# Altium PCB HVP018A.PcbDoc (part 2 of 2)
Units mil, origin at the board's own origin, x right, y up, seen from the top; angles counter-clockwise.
Board outline 2060 x 1591 mil, 4 copper layers (Top Layer, MidLayer1, MidLayer2, Bottom Layer), stack 46.2 mil thick; 91 components, 51 nets, 302 pads, 340 vias.
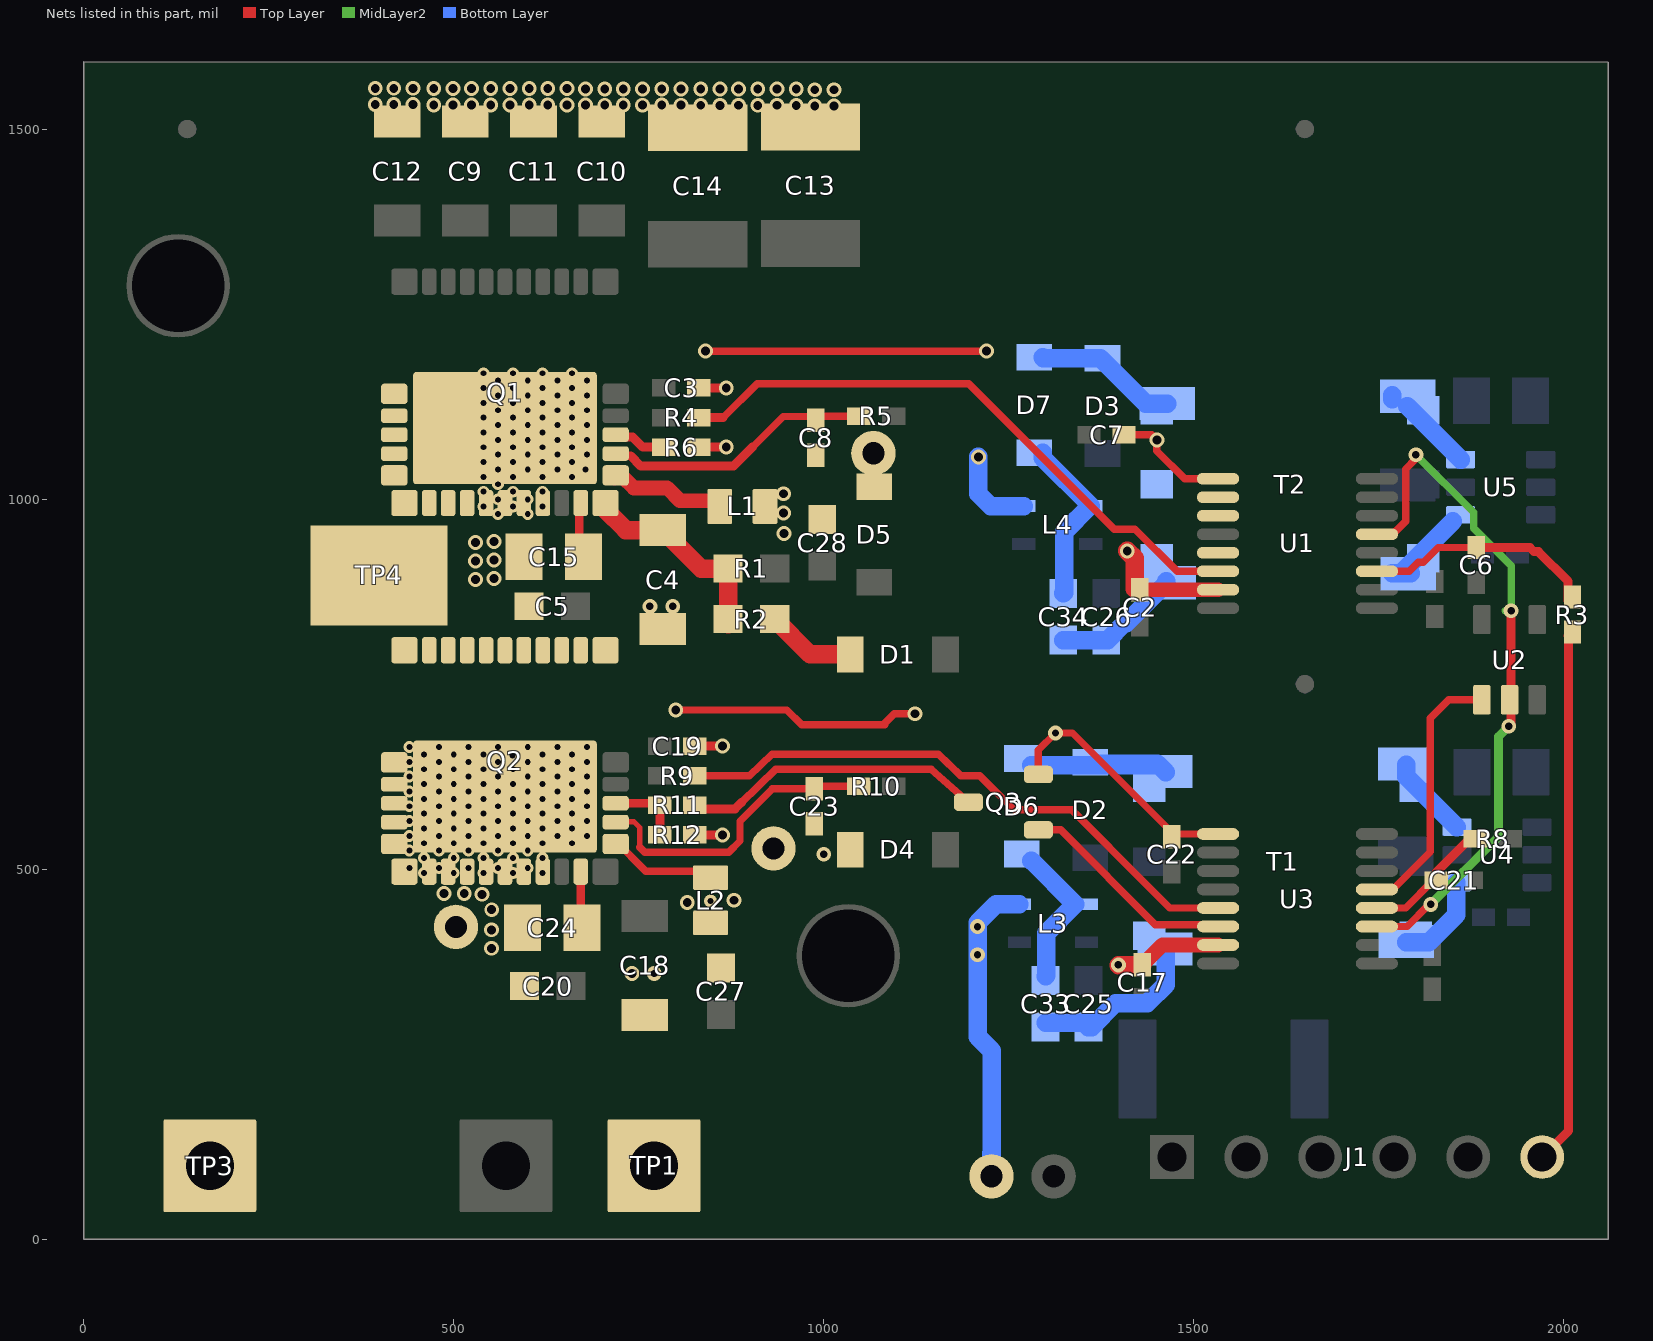
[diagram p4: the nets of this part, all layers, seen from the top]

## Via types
v1: diameter 16, hole 8, Top Layer to Bottom Layer, 182 vias
v2: diameter 20, hole 12, Top Layer to Bottom Layer, tented both sides, 80 vias
v3: diameter 20, hole 10, Top Layer to Bottom Layer, tented both sides, 40 vias
v4: diameter 20, hole 12, Top Layer to Bottom Layer, tented top, 18 vias
v5: diameter 20, hole 12.1, Top Layer to Bottom Layer, tented both sides, 14 vias
v6: diameter 20, hole 12, Top Layer to Bottom Layer, 4 vias
v7: diameter 22, hole 10, Top Layer to Bottom Layer, tented both sides, 1 vias
v8: diameter 18, hole 8, Top Layer to Bottom Layer, tented both sides, 1 vias

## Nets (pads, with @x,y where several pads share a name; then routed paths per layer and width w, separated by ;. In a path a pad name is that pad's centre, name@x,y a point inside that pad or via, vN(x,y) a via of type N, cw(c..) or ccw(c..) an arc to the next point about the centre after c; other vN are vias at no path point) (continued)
ISO_RET_H: C2.1 C3.1 C4.2 C5.2 C7.2 C8.2 C15.2 C28.2 D5.2 L1.1 L4.2 pad.2@1067,1062 Q1.12 Q1.13 Q1.14 Q1.15 Q1.16 Q1.17 Q1.18 Q1.19 Q1.20 Q1.21 Q1.22 Q1.23 Q1.24 Q1.33@569.24,1095.94 Q2.1 Q2.2 Q2.3 Q2.4 Q2.5 Q2.6 Q2.7 Q2.8 Q2.9 Q2.10 Q2.11 R6.1 TP3.1 TP4.1 U1.9 U1.15 | length 904.6
  Top Layer w10: v6(840,1200) v6(1220,1200) ; C7.2@1405.62,1087 1443,1087 v5(1450,1080) 1450,1078.52 1450,1065 1487.5,1027.5 1501.02,1027.5 U1.9@1532.72,1027.5 ; C2.1@1427,867.5 C2.1@1427,877.62
  Top Layer w12: R6.1@830.86,1070.17 v2(868.24,1070.17) ; C3.1@830.86,1150.17 v2(868.24,1150.17)
  Top Layer w20: C2.1@1427,877.62 U1.15@1532.59,877.62
  Top Layer w25: v5(1410,930) 1420,920 C2.1@1420,878.62
  Bottom Layer w25: v2(1209,1057) 1209,1007 1225.41,990.59 L4.2@1270.32,990.59
  other v1: 560,980 600,980 540,990 580,990 620,990 560,999.72 600,999.72 540,1010 580,1010 620,1010 560,1020 540,1030 580,1030 620,1030 660,1030 560,1040 600,1040 640,1040 678.26,1039.8 540,1050 580,1050 620,1050 660,1050 560,1060 600,1060 640,1060 680,1060 540,1070 580,1070 620,1070 660,1070 560,1080 600,1080 640,1080 680,1080 540,1090 580,1090 620,1090 660,1090 560,1100 600,1100 640,1100 680,1100 540,1110 580,1110 620,1110 660,1110 560,1120 600,1120 640,1120 680,1120 540,1130 580,1130 620,1130 660,1130 560,1140 600,1140 640,1140 680,1140 540,1150 580,1150 620,1150 660,1150 560,1160 600,1160 640,1160 680,1160 540,1170 580,1170 620,1170 660,1170
  other v2: 946.24,953.69 945.39,981.17 945.39,1007.17
  other v3: 765,855 796,855
  other v5: 529.24,891.53 554.24,892.63 529.24,916.53 554.24,917.63 529.24,941.53 554.24,942.63
ISO_RET_H_B: C34.2 D7.2 L4.3 | length 239.9
  Bottom Layer w25: C34.2@1323.59,872.5 1324.74,873.65 1324.74,955.72 1359.61,990.59 L4.3@1360.87,990.59 D7.2@1295.59,1055.87 ; D7.2@1295.59,1055.87 1295.59,1062.53 D7.2@1295.59,1055.87
ISO_RET_L: C9.2 C10.2 C11.2 C12.2 C13.2 C14.2 C17.1 C18.2 C19.1 C20.2 C22.2 C23.2 C24.2 C27.2 D4.2 L2.1 L3.2 pad.2@503,422 pad.2@932,528 pad.2@1226.59,85 Q2.12 Q2.13 Q2.14 Q2.15 Q2.16 Q2.17 Q2.18 Q2.19 Q2.20 Q2.21 Q2.22 Q2.23 Q2.24 Q2.33@569.24,597.94 Q3.2 R12.1 TP1.1 U3.9 U3.15 | length 1347.1
  Top Layer w10: v6(800,715) 949.88,715 970,695 1082.75,695 ; 1082.98,697.98 1095,710 v6(1123.35,710) ; Q3.2@1289.93,627.9 1289.93,660.93 v3(1313,684) 1336,684 1472.5,547.5 U3.9@1520.99,547.5
  Top Layer w12: R12.1@825.76,546.24 v2(863.14,546.24) ; C19.1@825.76,666.24 v2(863.14,666.24)
  Top Layer w20: C17.1@1430.59,370.62 1457.5,397.5 U3.15@1532.72,397.5
  Top Layer w25: v3@1398.47,370.3 C17.1@1430.09,370.3
  Bottom Layer w10: v3(1207.62,422.38) 1207.62,427.44 v3@1207.99,427.81
  Bottom Layer w25: pad.2@1226.59,85 1227,153 1227,254.59 1207.93,273.66 v3@1207.97,384.38 ; L3.2@1264.32,452.59 1232.99,452.81 1207.99,427.81 v3@1207.99,422.38 ; v3@1207.97,384.38 v3@1207.99,422.38 ; v3@1207.97,384.38 v3@1207.99,422.38
  other v1: 460,495 500,495 540,495 580,495 620,495 440,501.72 480,501.72 520,501.72 560,501.72 600,501.72 460,515 500,515 540,515 580,515 620,515 440,525 480,525 520,525 560,525 600,525 460,535 500,535 540,535 580,535 620,535 660,535 440,545 480,545 520,545 560,545 600,545 640,545 680,545 460,555 500,555 540,555 580,555 620,555 660,555 440,565 480,565 520,565 560,565 600,565 640,565 680,565 460,575 500,575 540,575 580,575 620,575 660,575 440,585 480,585 520,585 560,585 600,585 640,585 680,585 460,595 500,595 540,595 580,595 620,595 660,595 440,605 480,605 520,605 560,605 600,605 640,605 680,605 460,615 500,615 540,615 580,615 620,615 660,615 440,625 480,625 520,625 560,625 600,625 640,625 680,625 460,635 500,635 540,635 580,635 620,635 660,635 440,645 480,645 520,645 560,645 600,645 640,645 680,645 579.24,653.81 460,655 500,655 540,655 620,655 660,655 440,665 480,665 520,665 560,665 600,665 640,665 680,665
  other v2: 741,359 815.51,455 878.5,458 987.81,1531.04 1013.81,1531.09 704,1532.21 755,1532.21 807,1532.21 833.81,1532.09 859.81,1532.04 884.81,1532.09 910.81,1532.04 936.81,1532.09 962.81,1532.04 394,1532.95 419,1533 445,1532.95 473,1532.63 499,1532.58 524,1532.63 550,1532.58 576,1532.63 602,1532.58 627,1532.63 653,1532.58 678,1532.26 729,1532.26 781,1532.26 987.81,1553.09 1013.81,1553.09 833.81,1554.09 859.81,1554.09 884.81,1554.09 910.81,1554.09 936.81,1554.09 962.81,1554.09 394,1555 419,1555 445,1555 473,1554.63 499,1554.63 524,1554.63 550,1554.63 576,1554.63 602,1554.63 627,1554.63 653,1554.63 678,1554.26 704,1554.26 729,1554.26 755,1554.26 781,1554.26 807,1554.26
  other v3: 771,359 1398.09,370.68 1207.62,384.38 1000,520
  other v5: 551,393 551,418 551.24,445.17 538,466 487,467 514.24,467.17
  other v8: 847,457
ISO_RET_L_B: C33.2 D6.2 L3.3 | length 197
  Bottom Layer w25: D6.2@1280.59,511.53 1339.53,452.59 1300.44,413.5 1300.44,356.34 C33.2@1299.59,355.5
ISONC1: U1.10
ISONC2: U1.13
ISONC3: U1.11
ISONC4: T2.2
NetC4_1: C4.1 Q1.27 R1.2 R2.2 | length 274.4
  Top Layer w25: Q1.27@703.06,987.63 732.59,958.1 C4.1@782.24,958.1 834.17,906.17 R1.2@870.74,906.17 R2.2@870.74,837.92 ; R2.2@867.37,834.55 R2.2@870.74,831.17
NetC6_1: C6.1 R3.2 U1.3 | length 316.9
  Top Layer w10: U1.3@1747.28,902.5 1790.91,902.5 1803.28,914.87 1810.25,914.87 1830,934.62 C6.1@1881.59,934.62
  Top Layer w12: C6.1@1881.59,934.62 1954.21,934.62 1959.7,929.13 1965.46,929.13 2005.59,889 R3.2@2005.59,862.62
NetC8_1: C8.1 Q1.29 R5.2 | length 429.8
  Top Layer w10: 903.61,1070.17 945.06,1111.62 ; C8.1@989.38,1112 R5.2@1047.38,1112 ; 945.06,1111.62 989,1111.62 945.06,1111.62
  Top Layer w12: 903.61,1070.17 877.93,1044.49 752.92,1044.49 738.91,1058.5 ; 738.91,1058.5 716.84,1058.5 738.91,1058.5
NetC21_1: C21.1 R8.2 U3.4 | length 169.5
  Top Layer w10: U3.4@1747.28,447.5 1786.1,447.5 C21.1@1823.6,485 ; C21.1@1824.5,485 C21.1@1827.59,485
  Top Layer w12: C21.1@1827.59,485 1827.59,496.08 R8.2@1872.51,541
NetC23_1: C23.1 Q2.29 R10.2 | length 450.1
  Top Layer w7: Q2.29@711.75,567.5 Q2.29@715.24,564 ; 751.4,529.71 751.4,556.24 743.63,564 ; Q2.29@715.24,564 743.63,564 ; Q2.29@715.24,564 743.63,564
  Top Layer w10: 751.4,529.71 758.06,523.05 871.76,523.05 886.73,538.02 886.73,564.74 930.62,608.62 C23.1@987,608.62 ; C23.1@992.38,611 994.76,611 995.76,612 R10.2@1047.38,612 R10.2@1053.38,612
NetC25_2: C25.2 C33.1 pad.3@1460.95,392.08 T1.1 | length 308
  Bottom Layer w25: C25.2@1357.59,286.5 1361.8,286.5 1394.29,319 1437.15,319 1461.95,343.81 pad.3@1461.95,390.92 ; C25.2@1357.59,292.5 1299.59,292.5 C25.2@1357.59,292.5 ; C25.2@1357.59,292.5 1361.8,292.5 C25.2@1357.59,292.5 ; C25.2@1357.59,289.5 1361.8,289.5 C25.2@1357.59,289.5
NetC26_2: C26.2 C34.1 pad.3@1465.59,887 T2.1 | length 175.8
  Bottom Layer w25: C34.1@1323.59,809.5 C26.2@1381.59,809.5 1383.54,809.5 1406.47,832.44 1408.73,832.44 pad.3@1462.95,886.66 ; pad.3@1462.95,886.66 1462.95,888.92 pad.3@1462.95,886.66
NetD1_1: D1.1 R2.1 | length 116.3
  Top Layer w25: R2.1@933.73,837.92 981.48,790.17 D1.1@1030.22,790.17
NetD2_2: D2.2 D6.1 pad.3@1460.95,632.08 T1.3 | length 356.3
  Bottom Layer w25: pad.3@1448.56,640.47 D2.2@1370.59,640.47 ; pad.3@1460.95,632.08 1461.95,631.08 1450.56,642.47 1372.59,642.47 D2.2@1370.59,640.47 ; D2.2@1370.59,640.47 1280.59,640.47 D2.2@1370.59,640.47
NetD3_2: D3.2 D7.1 pad.3@1463.95,1129.08 T2.3 | length 281
  Bottom Layer w25: D7.1@1295.59,1191.47 1296.59,1190.47 D3.2@1373.59,1190.47 ; pad.3@1463.95,1129.08 T2.3@1434.98,1129.08 ; D3.2@1373.59,1190.47 T2.3@1434.98,1129.08 ; D3.2@1373.59,1190.47 T2.3@1434.98,1129.08
NetQ1_30: Q1.30 R6.2 | length 97.1
  Top Layer w12: R6.2@783.61,1070.17 755.34,1070.17 741.43,1084.09 ; 741.43,1084.09 716.84,1084.09 741.43,1084.09
NetQ2_30: Q2.30 R11.2 R12.2 | length 169.5
  Top Layer w12: Q2.30@711.75,593.09 Q2.30@715.83,589 ; R12.2@778.52,546.24 R11.2@778.52,586.24 R11.2@775.76,589 ; Q2.30@715.83,589 R11.2@775.76,589 ; Q2.30@715.83,589 R11.2@775.76,589
NetQ3_1: Q3.1 U3.14 | length 293.3
  Top Layer w10: Q3.1@1289.93,553.09 1319.91,553.09 1448,425 U3.14@1530.22,425
NetQ3_3: Q3.3 R11.1 | length 462.5
  Top Layer w10: 888.66,590 935,635 1145,635 Q3.3@1195.44,590.5
  Top Layer w12: 888.66,590 879.9,581.24 ; 879.9,581.24 825.76,581.24 879.9,581.24
NetR4_1: R4.1 U1.14 | length 825.8
  Top Layer w10: 864.17,1110.17 910,1156 1196,1156 1392.5,959.5 1420.5,959.5 1477.5,902.5 U1.14@1532.72,902.5
  Top Layer w12: R4.1@830.86,1110.17 864.17,1110.17
NetR9_1: R9.1 U3.13 | length 804
  Top Layer w10: R9.1@825.76,626.24 899.62,626.24 930,655 1155,655 1184.98,626.24 1210.76,626.24 1257,580 1335,580 1438,477 1467.5,447.5 U3.13@1532.72,447.5
NetT1_4: pad.3@1785.95,642.08 T1.4 U4.3 | length 112.6
  Bottom Layer w25: pad.3@1787.23,641.08 1787.23,624.98 U4.3@1855.46,556.75
NetT1_6: pad.3@1786.95,402.08 T1.6 U4.1 | length 126.2
  Bottom Layer w25: T1.6@1787.23,400.92 1817.51,400.92 1854.85,438.26 U4.1@1854.85,481.33
NetT2_4: pad.3@1788.95,1139.08 T2.4 U5.3 | length 113
  Bottom Layer w25: T2.4@1788.23,1125.63 U5.3@1860.46,1053.4 ; pad.3@1768.23,1134.63 1768.23,1140.08 pad.3@1768.23,1134.63
NetT2_6: pad.3@1789.45,899.08 T2.6 U5.1 | length 144.8
  Bottom Layer w25: pad.3@1782.32,902.32 U5.1@1850,970 ; pad.3@1768.23,899.92 1792.78,899.92 pad.3@1768.23,899.92
NetU1_5: U1.5 U2.2 U3.3 | length 922.4
  Top Layer w10: U3.3@1747.28,422.5 1788.17,422.5 1818.08,452.41 v3(1820,452.41) v3@1817.5,449.91 ; U1.5@1768.94,952.5 1786.33,969.89 1786.33,1040.66 1800,1054.33 v3(1800,1060)
  Top Layer w12: v3(1925.59,693) 1928.59,696 v3(1928.59,849)
  MidLayer2 w10: v3(1800,1060) 1878.09,981.91 1878.09,960.51 1928.59,910.01 v3(1928.59,849) v3@1921,849
  MidLayer2 w12: v3(1820,452.41) 1911.59,544 1911.59,679 v3(1925.59,693)
NetU2_1: U2.1 U3.5 | length 354
  Top Layer w10: U3.5@1747.28,472.5 1768.94,472.5 1819.59,523.15 1819.59,546 1819.59,704 1844.46,728.87 U2.1@1889.19,728.87
SW_H: L1.2 Q1.28 | length 164.1
  Top Layer w12: Q1.28@716.84,1024.61 Q1.28@716.84,1028.97
  Top Layer w20: L1.2@851,997.63 805.78,997.63 788.24,1015.17 743.24,1015.17 Q1.28@729.44,1028.97 ; Q1.28@729.44,1028.97 716.84,1028.97 717.39,1028.97 Q1.28@729.44,1028.97
SW_L: L2.2 Q2.28 | length 292.7
  Top Layer w10: Q2.28@718.97,538.03 759.66,497.34 ; Q2.28@718.97,538.03 718.51,538.03 Q2.28@718.97,538.03 ; Q2.28@718.97,538.03 759.66,497.34 ; 759.66,497.34 848,497.34 759.66,497.34
TOP_FET: J1.6 R3.1 | length 720.7
  Top Layer w12: J1.6@1970.59,111 2006.39,146.8 R3.1@2006.39,814.57 ; R3.1@2006.39,814.57 2005.59,815.38 R3.1@2006.39,814.57
VM12V_H: C15.1 Q1.26 | length 59.8
  Top Layer w12: C15.1@669.6,927.81 Q1.26@669.6,987.63
VM12V_L: C24.1 Q2.26 | length 55.8
  Top Layer w12: C24.1@663.73,441.17 C24.1@664.6,442.04 ; C24.1@671.6,442.04 Q2.26@671.6,496.57
pads on no net: FID1.1 FID2.1 FID3.1 FID4.1 FID5.1 FID6.1 LBL1.0 Q1.33@475.54,1060.94 Q1.33@475.54,1131.81 Q1.33@522.39,1060.94 Q1.33@522.39,1131.81 Q1.33@569.24,1060.94 Q1.33@569.24,1131.81 Q1.33@616.09,1060.94 Q1.33@616.09,1131.81 Q1.33@662.94,1060.94 Q1.33@662.94,1131.81 Q2.33@475.54,562.94 Q2.33@475.54,633.81 Q2.33@522.39,562.94 Q2.33@522.39,633.81 Q2.33@569.24,562.94 Q2.33@569.24,633.81 Q2.33@616.09,562.94 Q2.33@616.09,633.81 Q2.33@662.94,562.94 Q2.33@662.94,633.81 T1.2 U1.6 U1.7 U3.6 U3.7 U3.10 U3.11

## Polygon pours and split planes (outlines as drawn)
AGND on MidLayer1 "AGND_L02_P202" (solid, remove dead copper, pour order 202): 2046.59,63.59 2046.59,1315.41 2032,1330 1716.55,1330 1716.55,280.55 1608,172 1428.94,172 1419.59,162.65 1419.59,61.41 1431,50 2033,50
ISO_RET_L on MidLayer1 "ISO_RET_L_L02_P194" (solid, remove dead copper, pour order 194): 842.55,6.47 833.09,230.93 704.52,359.5 489.52,359.5 430.52,418.5 430.52,521 680.02,521 688.76,529.74 688.76,771.27 679.52,780.5 536.26,780.5 519.52,797.24 519.52,1120.5 760.52,1361.5 1053.52,1361.5 1059.52,1367.5 1059.52,1564.5 1051.35,1572.67 326.7,1572.67 315.52,1561.5 315.52,349.5 468.52,196.5 712.52,196.5 712.52,6.47
ISO_RET_L on MidLayer1 "MidLayer1-No Net 10" (solid, remove dead copper, pour order 152): 480.31,510 700,510 700,666 774,740 1506.99,740 1565,681.99 1565,271 1531,237 851,237 716.83,371.17 502.83,371.17 454,420 454,483.69
ISO_RET_H on MidLayer1 "MidLayer1-No Net" (solid, remove dead copper, pour order 150): 515,890.41 515,959.72 565.28,1010 698.2,1010 698.2,1149.2 774,1225 1513,1225 1563.46,1174.54 1563.46,832.46 1513,782 1295.05,782 1285,792.05 1285,824.98 1271.98,838 994.5,838 981.48,824.98 981.48,793.83 969.65,782 709.36,782 625.19,866.17 539.24,866.17
ISO_RET_H on MidLayer1 "MidLayer1-No Net 2" (solid, remove dead copper, pour order 148): 544.24,1183.17 692.24,1183.17 692.24,1013.17 533,1013.17 533,1183.17
ISO_RET_H on MidLayer1 "ISO_RET_H_L02_P222" (solid, remove dead copper, pour order 222): 111,8 99.73,19.26 99.73,124.73 105,130 235,130 241.46,123.54 241.46,17.46 232,8
HVBUS on MidLayer1 "HVBUS_L02_P228" (solid, remove dead copper, pour order 228): 511,8 499.73,19.26 499.73,124.73 505,130 635,130 641.46,123.54 641.46,17.46 632,8
ISO_RET_L on Bottom Layer "ISO_RET_L_L04_P216" (solid, remove dead copper, pour order 216): 315.76,679.83 315.76,344.24 338.17,321.83 676.83,321.83 825.76,470.76 825.76,671.83 744.76,752.83 388.76,752.83
ISO_RET_H on Bottom Layer "ISO_RET_H_L04_P214" (solid, remove dead copper, pour order 214): 316,1172 316,836.41 338.41,814 677.06,814 826,962.94 826,1164 745,1245 389,1245
AGND on Bottom Layer "AGND_L04_P072" (solid, remove dead copper, pour order 72): 1970.59,875 1990.59,875 2020.59,905 2020.59,1150 2005.59,1165 1930.59,1165 1920.59,1155 1920.59,890 1935.59,875
AGND on Bottom Layer "AGND_L04_P070" (solid, remove dead copper, pour order 70): 1924.59,401 1986.59,401 2014.59,429 2014.59,657 1976.7,694.89 1955.93,694.89 1923.59,662.54 1923.59,402
5V on Bottom Layer "5V_L04_P074" (solid, remove dead copper, pour order 74): 1752.6,1195 1879.59,1195 1905.59,1169 1905.59,310 1865.59,270 1780.59,270 1750.59,300 1750.59,1195
ISO_RET_H on Bottom Layer "ISO_RET_H_L04_P232" (solid, remove dead copper, pour order 232): 111,8 99.73,19.26 99.73,124.73 105,130 235,130 241.46,123.54 241.46,17.46 232,8
HVBUS on Bottom Layer "HVBUS_L04_P240" (solid, remove dead copper, pour order 240): 511,8 499.73,19.26 499.73,124.73 505,130 635,130 641.46,123.54 641.46,17.46 632,8
ISO_RET_L on Bottom Layer "ISO_RET_L_L04_P242" (solid, remove dead copper, pour order 242): 711,8 699.73,19.26 699.73,124.73 705,130 835,130 841.46,123.54 841.46,17.46 832,8
5V on MidLayer2 "5V_L03_P200" (solid, pour order 200): 2046.59,63.59 2046.59,1316.41 2033,1330 1730,1330 1730,294 1608,172 1428.94,172 1419.59,162.65 1419.59,61.41 1431,50 2033,50
ISO_RET_L on MidLayer2 "ISO_RET_L_L03_P198" (solid, remove dead copper, pour order 198): 841.46,-1 841.46,232.64 727.1,347 727.1,703 720.1,710 443.1,710 435.1,702 435.1,439 584.1,290 610.1,290 699.72,200.38 699.72,9 709.72,-1
HVBUS on MidLayer2 "HVBUS_L03_P190" (solid, remove dead copper, pour order 190): 650,10 650,200 393,457 393,721 279,835 279,1072 469,1262 1072,1262 1079,1269 1079,1395 1067,1407 267,1407 116,1256 116,764 220,660 220,420 499.72,140.28 499.72,10 630,10
ISO_RET_H on MidLayer2 "ISO_RET_H_L03_P158" (solid, remove dead copper, pour order 158): 747,1245 827,1165 827,935.94 762.24,871.17 534.24,871.17 515,890.41 515,1154 537.17,1176.17 601.17,1176.17 670,1245
ISO_RET_L on MidLayer2 "ISO_RET_L_L03_P142" (solid, remove dead copper, pour order 142): 526.24,709.88 526.24,393 726,393 798.03,465.03 798.03,701.97 790.12,709.88
ISO_RET_H on MidLayer2 "ISO_RET_H_L03_P238" (solid, remove dead copper, pour order 238): 111,8 99.73,19.26 99.73,124.73 105,130 235,130 241.46,123.54 241.46,17.46 232,8
ISO_RET_H on Top Layer "ISO_RET_H_L01_P182" (solid, remove dead copper, pour order 182): 241.46,17.46 241.46,216.54 214,244 214,699.61 291.48,777.08 732.62,777.08 732.62,830 640,830 620,850 620,1010 640,1030 701.24,1030 701.24,1193 411.49,1193 40,830 40,192 99.86,132.14 99.73,19.28 111,8 232,8
ISO_RET_L on Top Layer "ISO_RET_L_L01_P140" (solid, remove dead copper, pour order 140): 677.04,523.03 635.99,523 624,510.99 624,309 616,301 574,301 387,488 387,699 395.99,707.99 694,708.13 694,540.01
ISO_RET_L on Top Layer "ISO_RET_L_L01_P218" (solid, remove dead copper, pour order 218): 1119.29,472.16 1119.29,572.19 1104.48,587 928,587 898,557 898,484.63 886.37,473 812.51,473 805,465.49 805,405.07 830.28,379.79 830.28,378.64 831.09,377.83 831.09,348 840.09,339 931,339 935,343 935,445 962.16,472.16
ISO_RET_L on Top Layer "ISO_RET_L_L01_P186" (solid, remove dead copper, pour order 186): 727,301.5 727,370 789,370 789,301.5
ISO_RET_H on Top Layer "ISO_RET_H_L01_P184" (solid, remove dead copper, pour order 184): 751,803 751,866 814,866 814,803
HVBUS on Top Layer "HVBUS_L01_P170" (solid, remove dead copper, pour order 170): 1059.4,1391.3 1059.4,1275.3 1043.4,1259.3 389.83,1264.72 116,990.89 116,1164.1 165.95,1198.28 216.57,1356.87 267,1407.3 1043.4,1407.3
IN_L on Top Layer "IN_L_L01_P128" (solid, remove dead copper, pour order 128): 712.14,631 736.91,631 760.14,654.24 760.14,679 788,679 795.2,671.8 795.2,611.2 788,604 701,604 701,619.86
ISO_12V_L on Top Layer "ISO_12V_L_L01_P126" (solid, remove dead copper, pour order 126): 812,245 1024.72,245 1024.72,264.28 960.01,329 812,329
ISO_RET_L on Top Layer "ISO_RET_L_L01_P102" (solid, remove dead copper, pour order 102): 316,1481 316,1555 328,1567 1051,1567 1060,1558 1060,1485.39 1046.61,1472 325,1472
IN_H on Top Layer "IN_H_L01_P036" (solid, remove dead copper, pour order 36): 701.24,1123 751.56,1123 768.24,1139.67 768.24,1162.17 802.24,1162.17 802.24,1098.17 762.24,1098.17 738.24,1098.17 701.24,1098.17
ISO_RET_H on Top Layer "ISO_RET_H_L01_P067" (solid, remove dead copper, pour order 67): 902.24,1025.17 918.17,1025.17 973,1080 1212,1080 1228,1064 1228,988 1218.41,978.41 1042.41,978.41 1005.17,941.17 910.83,941.17 902.24,949.76
ISO_12V_H on Top Layer "ISO_12V_H_L01_P082" (solid, remove dead copper, pour order 82): 917.24,886.17 997.24,886.17 1010.41,873 1283,873 1292.68,882.68 1292.68,946.32 1287.83,951.17 1026.17,951.17 1004,929 916.36,929 912.24,924.87 912.24,891.17
HVBUS on Top Layer "HVBUS_L01_P224" (solid, remove dead copper, pour order 224): 511,8 499.73,19.26 499.73,124.73 505,130 635,130 641.46,123.54 641.46,17.46 632,8
ISO_RET_L on Top Layer "ISO_RET_L_L01_P226" (solid, remove dead copper, pour order 226): 711,8 699.73,19.26 699.73,124.73 705,130 835,130 841.46,123.54 841.46,17.46 832,8

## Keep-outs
Keep-Out Layer:
  lines w5: 0,1590 2060,1591 2060,0 0,0 0,1591
  text ".Layer_Name" at 452,-1396.77 h60

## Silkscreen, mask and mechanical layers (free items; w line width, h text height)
Top Overlay:
  lines w4: 860,568 875,578 ; 860,598 875,608 ; 860,637 875,647 ; 860.05,683 875.05,693 ; 862.63,1171.72 888.82,1179.62 ; 967,784 987,872 ; 1065,1329 1087,1301
  lines w5: 1743.59,154 1743.59,296
  text "HVP018A" at 1460,1385 h108.27
  text "Caution" at 85,740 h30
  text "High Voltage" at 15,690 h30
  text "VSW" at 105,190 h40
  text "VDC" at 515,185 h40
  text "PGND" at 695,185 h40
  text "Caution" at 1020,180 h30
  text "12V" at 1590.59,160 h40 r90
  text "5V" at 1690.59,160 h40 r90
  text "FAULT" at 1785.59,154 h30 r90
  text "Q1 Gate" at 1987.59,153 h35 r90
  text "Q2 Gate" at 1910,150.41 h35 r90
  text "Hot Surface" at 1040,140 h30
  text "V:480V / I:10A" at 255,120 h35
  text "AGND" at 1405,90 h40 r90
Bottom Overlay:
  lines w10: 5,1060 367,1420.36 ; 788,232.64 1185,628
  lines w20: 50,230 1180,230 ; 1181,235 1181,1424
  text "High Voltage" at 1825,340 h25
  text "Caution" at 1825,305 h25
  text "Hot Surface" at 1045,180 h30
  text "Caution" at 1040,140 h30
  text "V:480V / I:10A" at 485.59,-22 h35
Top Paste:
  text ".Layer_Name" at 452,-1396.77 h60
Bottom Paste:
  text ".Layer_Name" at 452,-1396.77 h60
Top Solder:
  text ".Layer_Name" at 452,-1396.77 h60
Bottom Solder:
  rectangle: 30,240 1181,1421.1
  text ".Layer_Name" at 452,-1396.77 h60
M1 Board Outline:
  lines w5: -160,1591 2060,1591 2060,0 ; 0,0 0,1591
  text ".Layer_Name" at 452,-1396.77 h60
M2 Board Dimensions:
  rectangle: -120,-823.28 5,-698.28
  rectangle: 0,-948.78 375,-823.78
  lines w7: -125,-698.78 -125,-948.78 875,-948.78 875,-698.78 ; -120,-823.28 880,-823.28 ; -120,-698.28 880,-698.28 ; 0,-948.78 0,-698.78 ; 125,-948.78 125,-698.78 ; 375,-948.78 375,-698.78 ; 625,-948.78 625,-698.78
  text ".Layer_Name" at 452,-1396.77 h60
M3 3D STEP Top:
  text ".Layer_Name" at 452,-1396.77 h60
M5 Assembly Top:
  lines w10: -417,-1468.44 6183,-1468.44 ; -417,-1265.11 6185,-1265.11 ; -417,-1061.78 -417,-1671.78 3588,-1671.78 6185,-1671.78 6185,-1061.78 -416.5,-1061.78 -416.5,-1671.78 1159,-1671.78 ; 2048,-1671.78 2048,-1061.78 ; 3315,-1265.11 3315,-1061.78 ; 4155,-1265.11 4155,-1061.78 ; 4777,-1678.28 4777,-1475.44
  text "COMPONENTS MARKED 'DNP' SHOULD NOT BE POPULATED." at 1028.5,-856.78 h60
  text "ASSEMBLY VARIANT:" at 1028,-972.28 h60
  text ".VariantName" at 2064,-972.28 h60
  text "PCB VIEWED FROM TOP SIDE" at -353.5,-1193.94 h60
  text "BOARD #:" at 2123,-1193.94 h60
  text ".PRJ_Number" at 2668.5,-1193.94 h60
  text "REV:" at 3513,-1193.94 h60
  text ".PCB_Rev" at 3804.5,-1193.94 h60
  text "SVN REV:" at 4351,-1193.94 h60
  text ".VersionControl_RevNumber" at 4857,-1193.94 h60
  text "IGNORE ->" at -353.5,-1396.77 h60
  text "PLOT NAME =" at -353.5,-1602.61 h60
  text ".plot_File_Name" at 452,-1602.61 h60
  text "GENERATED    :" at 2125,-1602.61 h60
  text ".Print_Date" at 2994.5,-1602.61 h60
  text ".Print_Time" at 3723.5,-1602.61 h60
  text "TEXAS INSTRUMENTS" at 4988,-1602.61 h60
M6 Assembly Bottom:
  lines w10: -417.5,-1265.61 6184.5,-1265.61 ; -415.5,-1468.94 6184.5,-1468.94 ; 990.5,-1678.78 990.5,-1475.94 ; 1612.5,-1265.61 1612.5,-1062.28 ; 2452.5,-1265.61 2452.5,-1062.28 ; 3719.5,-1672.28 3719.5,-1062.28 ; 4608.5,-1672.28 6184,-1672.28 6184,-1062.28 -417.5,-1062.28 -417.5,-1672.28 2179.5,-1672.28 6184.5,-1672.28 6184.5,-1062.28
  text "COMPONENTS MARKED 'DNP' SHOULD NOT BE POPULATED." at 6674,-860.28 h60
  text ".VariantName" at 5630,-976.28 h60
  text "ASSEMBLY VARIANT:" at 6669,-976.28 h60
  text ".VersionControl_RevNumber" at 910.5,-1194.44 h60
  text "SVN REV:" at 1416.5,-1194.44 h60
  text ".PCB_Rev" at 1963,-1194.44 h60
  text "REV:" at 2254.5,-1194.44 h60
  text ".PRJ_Number" at 3099,-1194.44 h60
  text "BOARD #:" at 3644.5,-1194.44 h60
  text "PCB VIEWED FROM BOTTOM SIDE" at 6121,-1194.44 h60
  text "IGNORE ->" at 2422.85,-1396.77 h60
  text "TEXAS INSTRUMENTS" at 779.5,-1603.11 h60
  text ".Print_Time" at 2044,-1603.11 h60
  text ".Print_Date" at 2773,-1603.11 h60
  text "GENERATED    :" at 3642.5,-1603.11 h60
  text ".plot_File_Name" at 5315.5,-1603.11 h60
  text "PLOT NAME =" at 6121,-1603.11 h60
M9 Title Sheet:
  drawing of 57 lines, arcs and shapes, not listed
  text "1" at 614.84,7498.22 h70
  text "2" at 3110.5,7498.22 h70
  text "3" at 5599.84,7498.22 h70
  text "4" at 8106.51,7498.22 h70
  text "5" at 10605.5,7498.22 h70
  text "6" at 13110.5,7498.22 h70
  text "A" at -541.5,6355.22 h70
  text "A" at 14258.5,6355.22 h70
  text "B" at -541.5,3975.22 h70
  text "B" at 14258.5,3975.22 h70
  text "C" at 14258.5,1600.22 h70
  text "PROJECT TITLE:" at 11218.5,-260.78 h45
  text "LMG3410-HB-EVM-18" at 11268.5,-394.1 h70
  text "DESIGNED FOR:" at 11218.5,-561.78 h45
  text ".PRJ_Customer" at 11268.5,-701.78 h70
  text "D" at -541.5,-769.78 h70
  text "D" at 14258.5,-769.78 h70
  text "FILE NAME:" at 11218.5,-861.78 h45
  text ".PCB_File_Name_No_Path" at 11268.5,-981.78 h70
  text "Texas Instruments (TI) and/or its licensors do not warrant the accuracy or completeness of this specification" at 6249,-1143.61 h45
  text "ENGINEER:" at 11218.5,-1151.78 h45
  text "LAYOUT BY:" at 12723.5,-1151.78 h45
  text "or any information contained therein. TI and/or its licensors do not warrant that this design will meet" at 6204.01,-1256.28 h45
  text "Rui Gao" at 11268.5,-1306.77 h70
  text "Rui Gao" at 12774,-1306.77 h70
  text "the specifications, will be suitable for your application or fit for any particular purpose, or will operate in" at 6204.01,-1368.94 h45
  text ".Layer_Name" at 452,-1396.77 h60
  text "ALTIUM DESIGNER VERSION:" at 12723.5,-1461.78 h45
  text "an implementation. TI and/or its licensors do not warrant that the design is production worthy. You should" at 6204.01,-1481.61 h45
  text "completely validate and test your design implementation to confirm the system functionality for your application." at 6249,-1594.28 h45
  text ".print_Scale" at 11268.5,-1595.1 h70
  text ".Application_BuildNumber" at 12774,-1595.1 h70
  text "1" at 614.84,-1801.78 h70
  text "2" at 3110.5,-1801.78 h70
  text "3" at 5599.84,-1801.78 h70
  text "4" at 8106.51,-1801.78 h70
  text "5" at 10605.5,-1801.78 h70
  text "6" at 13110.5,-1801.78 h70
M10 Fab Notes:
  drawing of 186 lines, arcs and shapes, not listed
  text "DESIGN INFORMATION" at 12256.02,5371.72 h60
  text "MIN. TRACK WIDTH:" at 11611.46,5191.72 h60
  text "6" at 12707.7,5191.73 h60
  text "MIL" at 12862.46,5191.72 h60
  text "MIN. CLEARANCE:" at 11611.46,5059.72 h60
  text "5.5" at 12647.7,5059.73 h60
  text "MIL" at 12862.46,5059.72 h60
  text "MIN. VIA PAD SIZE:" at 11611.46,4927.72 h60
  text "16" at 12677.71,4927.73 h60
  text "MIL" at 12862.46,4927.72 h60
  text "4 MIL" at 12306.46,4786.01 h60
  text "MINIMUM ANNULAR RING" at 11282.23,4781.73 h60
  text "PER" at 11482.23,4663.73 h60
  text "IPC-D-275 CLASS 2 LEVEL C" at 11702.23,4663.72 h60
  text "MIL, HOLES" at 13190.46,4551.44 h60
  text "+/-" at 12798,4550.73 h60
  text "+/-" at 13652,4550.73 h60
  text "REGISTRATION TOLERANCES:" at 11282.23,4545.72 h60
  text "METAL" at 12482,4545.72 h60
  text "MIL" at 14007.46,4545.72 h60
  text "MATERIAL:" at 11207.46,4336.27 h60
  text "FR-4 High Tg" at 12193.9,4195.93 h60
  text "FR-408" at 11628.46,4187.36 h60
  text "X" at 12040.46,4187.36 h60
  text "OTHER" at 13116.46,4187.36 h60
  text "62 MIL (1.6mm) +/-10%" at 11948.56,4024.65 h60
  text "47 MIL +/-10%" at 13530.56,4024.65 h60
  text "THICKNESS:" at 11282.23,4020.36 h60
  text "OTHER" at 13233.46,4020.36 h60
  text "X" at 13100.46,4016.36 h60
  text "TOLERANCE:" at 11282.23,3862.36 h60
  text "X" at 12121.53,3862.36 h60
  text "ANSI IPC-6012 TYPE 3 CLASS 2" at 12308.48,3862.36 h60
  text "OTHER +/-" at 12308.46,3706.36 h60
  text "BOW & TWIST:" at 11282.23,3549.36 h60
  text "X" at 12121.53,3549.36 h60
  text "ANSI IPC-6012 TYPE 3 CLASS 2" at 12308.48,3549.36 h60
  text "OTHER +/-" at 12308.46,3390.86 h60
  text "DRILLING:" at 11207.46,3252.36 h60
  text "REFERENCE:" at 11282.23,3135.36 h60
  text "X" at 11930.46,3135.36 h60
  text "AS SHOWN" at 12117.46,3135.36 h60
  text "X" at 12831.46,3135.36 h60
  text "NC_DRILL FILES" at 12968.46,3135.36 h60
  text "PTH MIN COPPER THICKNESS:" at 11282.23,2977.36 h60
  text "X" at 12624.46,2977.36 h60
  text "1MIL" at 12769.46,2977.36 h60
  text "OTHER" at 13266.46,2977.36 h60
  text "BOARD FINISH:" at 11207.46,2818.36 h60
  text "SILKSCREEN:" at 11362.68,2700.36 h60
  text "X" at 12311.46,2700.36 h60
  text "TOP" at 12437.46,2700.36 h60
  text "X" at 12821.46,2700.36 h60
  text "BOTTOM" at 12948.46,2700.36 h60
  text "SILKSCREEN COLOR:" at 11362.68,2533.36 h60
  text "X" at 12310.42,2533.36 h60
  text "WHITE" at 12437.46,2533.36 h60
  text "OTHER" at 12948.46,2533.36 h60
  text "SOLDER RESIST COLOR:" at 11362.68,2363.36 h60
  text "X" at 11930.42,2204.17 h60
  text "GREEN" at 12057.46,2204.17 h60
  text "BLUE" at 12648.46,2204.17 h60
  text "OTHER" at 13186.46,2204.17 h60
  text "IMMERSION GOLD (ENIG)" at 12268.46,2015.65 h60
  text "ENEPIG" at 13606,2012.36 h60
  text "SURFACE FINISH:" at 11207.46,2011.36 h60
  text "X" at 12081.51,2011.36 h60
  text "IMM. TIN/SILVER OR EQUIV" at 11537,1854.36 h60
  text "OTHER" at 12968.46,1854.36 h60
  text "Please fill all 8 mil vias and plate & polish flat." at 241.78,1736.72 h72.83
  text "1" at 96.78,1731.72 h72.83
  text "ARRAY/PANEL:" at 11207.46,1675.36 h60
  text "CUT AND TRIM PER MECH LAYER 1" at 12268.46,1671.08 h60
  text "N.C. ROUTE" at 12268.46,1519.36 h60
  text "X" at 12947.46,1519.36 h60
  text "V. SCORE" at 13134.46,1519.36 h60
  text "CERTIFICATION:" at 11207.46,1382.36 h60
  text "MATERIALS AND WORKMANSHIP FOR ALL PCBS" at 11932.46,1382.36 h60
  text "TO MEET OR EXCEED THE REQUIREMENTS OF:" at 11932.46,1284.36 h60
  text "X" at 11558.96,1147.86 h60
  text "ANSI IPC-A-600F CLASS ->" at 11697.96,1147.86 h60
  text "X" at 13337.02,1147.86 h60
  text "2" at 13455.96,1147.86 h60
  text "1" at 13140.96,1146.36 h60
  text "3" at 13809.96,1146.36 h60
  text "X" at 11561.02,988.36 h60
  text "UL 94V-0" at 11697.96,988.36 h60
  text "X" at 12373.02,988.36 h60
  text "RoHS" at 12509.96,988.36 h60
  text "OTHER" at 13154.36,988.36 h60
  text "PER ORDER" at 13551.42,988.36 h60
  text "ADDITIONAL REQUIREMENTS:" at 11207.46,847.36 h60
  text "MICROSECTION:" at 11282.23,732.36 h60
  text "YES" at 12187.96,732.36 h60
  text "REQUIRED" at 13049.46,576.22 h60
  text "BARE BOARD ELEC. TEST:" at 11282.23,573.36 h60
  text "NONE" at 12587.96,573.36 h60
  text "X" at 12922.46,573.36 h60
  text "PER ORDER" at 13641.46,573.36 h60
  text "MANUFACTURER'S UL:" at 11282.23,416.36 h60
  text "RAIL" at 12447.96,412.08 h60
  text "METAL" at 12939.77,412.08 h60
  text "X" at 13315,411.72 h60
  text "SILK" at 13451.46,412.08 h60
  text ".Layer_Name" at 452,-1396.77 h60
M11 Gerber Information:
  lines w10: -417,-1468.44 6183,-1468.44 ; -417,-1265.11 6185,-1265.11 ; -417,-1061.78 -417,-1671.78 3588,-1671.78 6185,-1671.78 6185,-1061.78 -416.5,-1061.78 -416.5,-1671.78 1159,-1671.78 ; 2048,-1671.78 2048,-1061.78 ; 3315,-1265.11 3315,-1061.78 ; 4155,-1265.11 4155,-1061.78 ; 4777,-1678.28 4777,-1475.44
  text "BOARD #:" at 2123,-1193.94 h60
  text ".PRJ_Number" at 2668.5,-1193.94 h60
  text "REV:" at 3513,-1193.94 h60
  text ".PCB_Rev" at 3804.5,-1193.94 h60
  text "SVN REV:" at 4351,-1193.94 h60
  text ".VersionControl_RevNumber" at 4857,-1193.94 h60
  text "PLOT NAME =" at -353.5,-1602.61 h60
  text ".plot_File_Name" at 452,-1602.61 h60
  text "GENERATED    :" at 2125,-1602.61 h60
  text ".Print_Date" at 2994.5,-1602.61 h60
  text ".Print_Time" at 3723.5,-1602.61 h60
  text "TEXAS INSTRUMENTS" at 4988,-1602.61 h60
M12 Stackup:
  drawing of 295 lines, arcs and shapes, not listed
  text "Layer" at 9492.84,7134.22 h60
  text "Name" at 9902.76,7134.22 h60
  text "Material" at 10832.5,7134.22 h60
  text "Thickness" at 11692.27,7134.22 h60
  text "Constant" at 12342.1,7134.22 h60
  text "Board Layer Stack" at 12911.96,7134.22 h60
  text "1" at 9492.84,7014.22 h60
  text "Top Overlay" at 9902.76,7014.22 h60
  text "2" at 9492.84,6894.22 h60
  text "Top Solder" at 9902.76,6894.22 h60
  text "Solder Resist" at 10832.5,6894.22 h60
  text "0.40mil" at 11692.27,6894.22 h60
  text "3.5" at 12342.1,6894.22 h60
  text "3" at 9492.84,6774.22 h60
  text "Top Layer" at 9902.76,6774.22 h60
  text "Copper" at 10832.5,6774.22 h60
  text "2.80mil" at 11692.27,6774.22 h60
  text "4" at 9492.84,6654.22 h60
  text "Dielectric1" at 9902.76,6654.22 h60
  text "FR-4 High Tg" at 10832.5,6654.22 h60
  text "4.60mil" at 11692.27,6654.22 h60
  text "4.8" at 12342.1,6654.22 h60
  text "5" at 9492.84,6534.22 h60
  text "MidLayer1" at 9902.76,6534.22 h60
  text "Copper" at 10832.5,6534.22 h60
  text "2.80mil" at 11692.27,6534.22 h60
  text "6" at 9492.84,6414.22 h60
  text "Dielectric2" at 9902.76,6414.22 h60
  text "FR-4 High Tg" at 10832.5,6414.22 h60
  text "25.80mil" at 11692.27,6414.22 h60
  text "4.8" at 12342.1,6414.22 h60
  text "7" at 9492.84,6294.22 h60
  text "MidLayer2" at 9902.76,6294.22 h60
  text "Copper" at 10832.5,6294.22 h60
  text "2.80mil" at 11692.27,6294.22 h60
  text "8" at 9492.84,6174.22 h60
  text "Dielectric3" at 9902.76,6174.22 h60
  text "FR-4 High Tg" at 10832.5,6174.22 h60
  text "4.60mil" at 11692.27,6174.22 h60
  text "4.8" at 12342.1,6174.22 h60
  text "9" at 9492.84,6054.22 h60
  text "Bottom Layer" at 9902.76,6054.22 h60
  text "Copper" at 10832.5,6054.22 h60
  text "2.80mil" at 11692.27,6054.22 h60
  text "10" at 9492.84,5934.22 h60
  text "Bottom Solder" at 9902.76,5934.22 h60
  text "Solder Resist" at 10832.5,5934.22 h60
  text "0.40mil" at 11692.27,5934.22 h60
  text "3.5" at 12342.1,5934.22 h60
  text "11" at 9492.84,5814.22 h60
  text "Bottom Overlay" at 9902.76,5814.22 h60
  text ".Layer_Name" at 452,-1396.77 h60
M13 Component Bodies Top:
  text ".Layer_Name" at 452,-1396.77 h60
M14 Component Bodies Bottom:
  text ".Layer_Name" at 452,-1396.77 h60
M15 Courtyards Top:
  text ".Layer_Name" at 452,-1396.77 h60
M16 Courtyards Bottom:
  text ".Layer_Name" at 452,-1396.77 h60
Drill Drawing:
  circle w10: c3719.72,315.73 r27.63
  lines w10: 3692.09,-71.05 3705.9,-71.05 3719.72,-84.86 3733.53,-71.05 3747.34,-71.05 3733.53,-57.23 3747.34,-43.42 3733.53,-43.42 3719.72,-29.61 3705.9,-43.42 3692.09,-43.42 3705.9,-57.23 3692.09,-71.05 ; 3692.09,67.09 3719.72,39.46 3747.34,67.09 3719.72,94.71 3692.09,67.09 ; 3692.09,219.03 3747.34,219.03 3719.72,163.78 3692.09,219.03 ; 3692.09,412.42 3747.34,412.42 3747.34,467.67 3692.09,467.67 3692.09,412.42 ; 3692.09,550.55 3705.9,550.55 3705.9,536.74 3733.53,536.74 3733.53,550.55 3747.34,550.55 3747.34,578.18 3733.53,578.18 3733.53,591.99 3705.9,591.99 3705.9,578.18 3692.09,578.18 3692.09,550.55 ; 3692.09,661.06 3747.34,661.06 3747.34,716.31 3692.09,716.31 3692.09,661.06 ; 3692.09,785.38 3692.09,799.19 3705.9,813.01 3692.09,826.82 3692.09,840.63 3705.9,840.63 3719.72,826.82 3733.53,840.63 3747.34,840.63 3747.34,826.82 3733.53,813.01 3747.34,799.19 3747.34,785.38 3733.53,785.38 3719.72,799.19 3705.9,785.38 3692.09,785.38 ; 3703.14,423.47 3736.29,423.47 3736.29,456.62 3703.14,456.62 3703.14,423.47
  lines w12: 3642,-122.16 6719.24,-122.16 ; 3642,872.4 6719.24,872.4 ; 3979.86,-246.48 3979.86,996.72 ; 4311.86,-246.48 4311.86,996.72 ; 4948.43,-246.48 4948.43,996.72 ; 5207.57,-246.48 5207.57,996.72 ; 5582.72,-246.48 5582.72,996.72 ; 6307.05,-246.48 6307.05,996.72 ; 3642,-246.48 6719.24,-246.48 6719.24,996.72 3642,996.72 3642,-246.48
  text "Symbol" at 3716.59,909.7 h72
  text "Quantity" at 4017.16,909.7 h72
  text "Finished Hole Size" at 4349.16,909.7 h72
  text "Plated" at 4985.72,909.7 h72
  text "Hole Type" at 5244.86,909.7 h72
  text "Drill Layer Pair" at 5620.02,909.7 h72
  text "Tolerance" at 6344.35,909.7 h72
  text "183" at 4017.16,785.38 h60
  text "8.00mil (0.203mm)" at 4349.16,785.38 h60
  text "PTH" at 4985.72,785.38 h60
  text "Round" at 5244.86,785.38 h60
  text "Top Layer - Bottom Layer" at 5620.02,785.38 h60
  text "41" at 4017.16,661.06 h60
  text "10.00mil (0.254mm)" at 4349.16,661.06 h60
  text "PTH" at 4985.72,661.06 h60
  text "Round" at 5244.86,661.06 h60
  text "Top Layer - Bottom Layer" at 5620.02,661.06 h60
  text "102" at 4017.16,536.74 h60
  text "12.00mil (0.305mm)" at 4349.16,536.74 h60
  text "PTH" at 4985.72,536.74 h60
  text "Round" at 5244.86,536.74 h60
  text "Top Layer - Bottom Layer" at 5620.02,536.74 h60
  text "14" at 4017.16,412.42 h60
  text "12.10mil (0.307mm)" at 4349.16,412.42 h60
  text "PTH" at 4985.72,412.42 h60
  text "Round" at 5244.86,412.42 h60
  text "Top Layer - Bottom Layer" at 5620.02,412.42 h60
  text "5" at 4017.16,288.1 h60
  text "30.00mil (0.762mm)" at 4349.16,288.1 h60
  text "PTH" at 4985.72,288.1 h60
  text "Round" at 5244.86,288.1 h60
  text "Top Layer - Bottom Layer" at 5620.02,288.1 h60
  text "6" at 4017.16,163.78 h60
  text "39.37mil (1.000mm)" at 4349.16,163.78 h60
  text "PTH" at 4985.72,163.78 h60
  text "Round" at 5244.86,163.78 h60
  text "Top Layer - Bottom Layer" at 5620.02,163.78 h60
  text "3" at 4017.16,39.46 h60
  text "64.96mil (1.650mm)" at 4349.16,39.46 h60
  text "PTH" at 4985.72,39.46 h60
  text "Round" at 5244.86,39.46 h60
  text "Top Layer - Bottom Layer" at 5620.02,39.46 h60
  text "2" at 4017.16,-84.86 h60
  text "125.00mil (3.175mm)" at 4349.16,-84.86 h60
  text "PTH" at 4985.72,-84.86 h60
  text "Round" at 5244.86,-84.86 h60
  text "Top Layer - Bottom Layer" at 5620.02,-84.86 h60
  text "356 Total" at 4017.16,-209.18 h60
  text ".Layer_Name" at 452,-1396.77 h60

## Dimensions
-125,-948.78 to 875,-948.78 on M2 Board Dimensions
0,0 to 2060,0 on M2 Board Dimensions
0,1591 to 0,0 on M2 Board Dimensions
